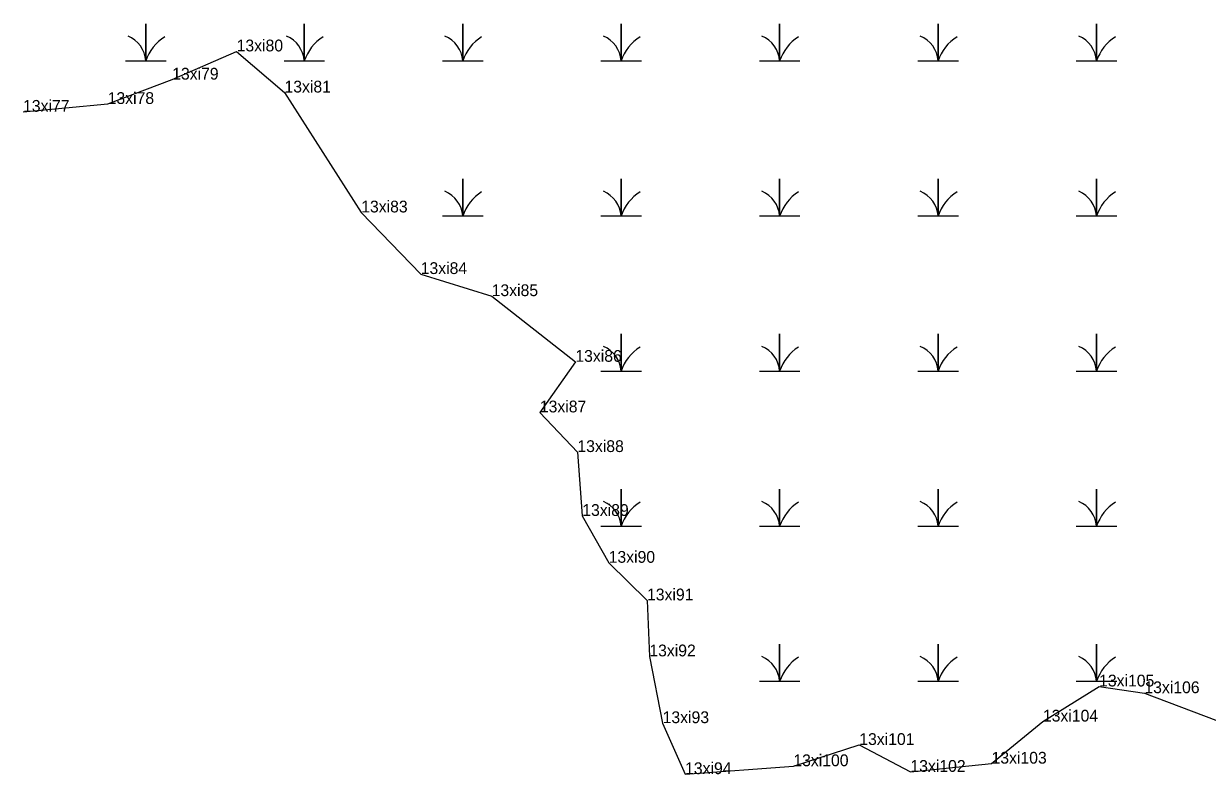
# Model space of a CAD drawing. Extents: x 2072529 to 2268796, y 436423 to 470406.
# Drawn here: x 2249251 to 2249753, y 445903 to 446222 of the extents above; entities that cross this region are included whole.
import ezdxf

# ---------------------------------------------------------------- set-up
doc = ezdxf.new("R2010")
doc.units = 0
for name, color, linetype in [('Exist Environmental Wetland Boundary Cogo Comment', 7, 'Continuous'), ('Exist Environmental Wetland Boundary Cogo Point CELL', 7, 'Continuous'), ('Old_Level_20', 7, 'Continuous')]:
    doc.layers.add(name, color=color, linetype=linetype)

msp = doc.modelspace()

# ---------------------------------------------------------------- linework, layer by layer
at = {"layer": 'Exist Environmental Wetland Boundary Cogo Point CELL'}
for points in [[(2249294.26, 446205.77), (2249302.86, 446205.77), (2249302.86, 446221.55), (2249302.86, 446205.77), (2249311.47, 446205.77)], [(2249361.51, 446205.77), (2249370.11, 446205.77), (2249370.11, 446221.55), (2249370.11, 446205.77), (2249378.72, 446205.77)], [(2249428.76, 446205.77), (2249437.36, 446205.77), (2249437.36, 446221.55), (2249437.36, 446205.77), (2249445.97, 446205.77)], [(2249496.01, 446205.77), (2249504.61, 446205.77), (2249504.61, 446221.55), (2249504.61, 446205.77), (2249513.22, 446205.77)], [(2249563.26, 446205.77), (2249571.86, 446205.77), (2249571.86, 446221.55), (2249571.86, 446205.77), (2249580.47, 446205.77)], [(2249630.51, 446205.77), (2249639.11, 446205.77), (2249639.11, 446221.55), (2249639.11, 446205.77), (2249647.72, 446205.77)], [(2249697.76, 446205.77), (2249706.36, 446205.77), (2249706.36, 446221.55), (2249706.36, 446205.77), (2249714.97, 446205.77)], [(2249428.76, 446139.97), (2249437.36, 446139.97), (2249437.36, 446155.75), (2249437.36, 446139.97), (2249445.97, 446139.97)], [(2249496.01, 446139.97), (2249504.61, 446139.97), (2249504.61, 446155.75), (2249504.61, 446139.97), (2249513.22, 446139.97)], [(2249563.26, 446139.97), (2249571.86, 446139.97), (2249571.86, 446155.75), (2249571.86, 446139.97), (2249580.47, 446139.97)], [(2249630.51, 446139.97), (2249639.11, 446139.97), (2249639.11, 446155.75), (2249639.11, 446139.97), (2249647.72, 446139.97)], [(2249697.76, 446139.97), (2249706.36, 446139.97), (2249706.36, 446155.75), (2249706.36, 446139.97), (2249714.97, 446139.97)], [(2249496.01, 446074.17), (2249504.61, 446074.17), (2249504.61, 446089.95), (2249504.61, 446074.17), (2249513.22, 446074.17)], [(2249563.26, 446074.17), (2249571.86, 446074.17), (2249571.86, 446089.95), (2249571.86, 446074.17), (2249580.47, 446074.17)], [(2249630.51, 446074.17), (2249639.11, 446074.17), (2249639.11, 446089.95), (2249639.11, 446074.17), (2249647.72, 446074.17)], [(2249697.76, 446074.17), (2249706.36, 446074.17), (2249706.36, 446089.95), (2249706.36, 446074.17), (2249714.97, 446074.17)], [(2249496.01, 446008.37), (2249504.61, 446008.37), (2249504.61, 446024.15), (2249504.61, 446008.37), (2249513.22, 446008.37)], [(2249563.26, 446008.37), (2249571.86, 446008.37), (2249571.86, 446024.15), (2249571.86, 446008.37), (2249580.47, 446008.37)], [(2249630.51, 446008.37), (2249639.11, 446008.37), (2249639.11, 446024.15), (2249639.11, 446008.37), (2249647.72, 446008.37)], [(2249697.76, 446008.37), (2249706.36, 446008.37), (2249706.36, 446024.15), (2249706.36, 446008.37), (2249714.97, 446008.37)], [(2249563.26, 445942.57), (2249571.86, 445942.57), (2249571.86, 445958.35), (2249571.86, 445942.57), (2249580.47, 445942.57)], [(2249630.51, 445942.57), (2249639.11, 445942.57), (2249639.11, 445958.35), (2249639.11, 445942.57), (2249647.72, 445942.57)], [(2249697.76, 445942.57), (2249706.36, 445942.57), (2249706.36, 445958.35), (2249706.36, 445942.57), (2249714.97, 445942.57)]]:
    msp.add_lwpolyline(points, dxfattribs=at)
for centre, radius, start, end in [((2249290.6, 446204.88), 12.3, 4.1403, 67.535), ((2249321.11, 446199.7), 19.22, 122.1274, 161.6222), ((2249357.85, 446204.88), 12.3, 4.1403, 67.535), ((2249388.36, 446199.7), 19.22, 122.1274, 161.6222), ((2249425.1, 446204.88), 12.3, 4.1403, 67.535), ((2249455.61, 446199.7), 19.22, 122.1274, 161.6222), ((2249492.35, 446204.88), 12.3, 4.1403, 67.535), ((2249522.86, 446199.7), 19.22, 122.1274, 161.6222), ((2249559.6, 446204.88), 12.3, 4.1403, 67.535), ((2249590.11, 446199.7), 19.22, 122.1274, 161.6222), ((2249626.85, 446204.88), 12.3, 4.1403, 67.535), ((2249657.36, 446199.7), 19.22, 122.1274, 161.6222), ((2249694.1, 446204.88), 12.3, 4.1403, 67.535), ((2249724.61, 446199.7), 19.22, 122.1274, 161.6222), ((2249425.1, 446139.08), 12.3, 4.1403, 67.535), ((2249455.61, 446133.9), 19.22, 122.1274, 161.6222), ((2249492.35, 446139.08), 12.3, 4.1403, 67.535), ((2249522.86, 446133.9), 19.22, 122.1274, 161.6222), ((2249559.6, 446139.08), 12.3, 4.1403, 67.535), ((2249590.11, 446133.9), 19.22, 122.1274, 161.6222), ((2249626.85, 446139.08), 12.3, 4.1403, 67.535), ((2249657.36, 446133.9), 19.22, 122.1274, 161.6222), ((2249694.1, 446139.08), 12.3, 4.1403, 67.535), ((2249724.61, 446133.9), 19.22, 122.1274, 161.6222), ((2249492.35, 446073.28), 12.3, 4.1403, 67.535), ((2249522.86, 446068.1), 19.22, 122.1274, 161.6222), ((2249559.6, 446073.28), 12.3, 4.1403, 67.535), ((2249590.11, 446068.1), 19.22, 122.1274, 161.6222), ((2249626.85, 446073.28), 12.3, 4.1403, 67.535), ((2249657.36, 446068.1), 19.22, 122.1274, 161.6222), ((2249694.1, 446073.28), 12.3, 4.1403, 67.535), ((2249724.61, 446068.1), 19.22, 122.1274, 161.6222), ((2249492.35, 446007.48), 12.3, 4.1403, 67.535), ((2249522.86, 446002.3), 19.22, 122.1274, 161.6222), ((2249559.6, 446007.48), 12.3, 4.1403, 67.535), ((2249590.11, 446002.3), 19.22, 122.1274, 161.6222), ((2249626.85, 446007.48), 12.3, 4.1403, 67.535), ((2249657.36, 446002.3), 19.22, 122.1274, 161.6222), ((2249694.1, 446007.48), 12.3, 4.1403, 67.535), ((2249724.61, 446002.3), 19.22, 122.1274, 161.6222), ((2249559.6, 445941.68), 12.3, 4.1403, 67.535), ((2249590.11, 445936.5), 19.22, 122.1274, 161.6222), ((2249626.85, 445941.68), 12.3, 4.1403, 67.535), ((2249657.36, 445936.5), 19.22, 122.1274, 161.6222), ((2249694.1, 445941.68), 12.3, 4.1403, 67.535), ((2249724.61, 445936.5), 19.22, 122.1274, 161.6222)]:
    msp.add_arc(centre, radius, start, end, dxfattribs=at)
at = {"layer": 'Old_Level_20'}
for p, q in [((2249341.41, 446209.79), (2249341.41, 446209.79)), ((2249314.05, 446197.82), (2249314.05, 446197.82)), ((2249361.72, 446192.35), (2249361.72, 446192.35)), ((2249286.67, 446187.49), (2249286.67, 446187.49)), ((2249394.28, 446141.46), (2249394.28, 446141.46)), ((2249419.53, 446115.35), (2249419.53, 446115.35)), ((2249449.65, 446105.97), (2249449.65, 446105.97)), ((2249485.16, 446078.11), (2249485.16, 446078.11)), ((2249470.1, 446056.65), (2249470.1, 446056.65)), ((2249486.03, 446039.83), (2249486.03, 446039.83)), ((2249488.1, 446012.73), (2249488.1, 446012.73)), ((2249499.3, 445992.85), (2249499.3, 445992.85)), ((2249515.58, 445976.9), (2249515.58, 445976.9)), ((2249516.56, 445953.16), (2249516.56, 445953.16)), ((2249707.45, 445940.39), (2249707.45, 445940.39)), ((2249726.67, 445937.54), (2249726.67, 445937.54)), ((2249683.6, 445925.5), (2249683.6, 445925.5)), ((2249522.21, 445924.83), (2249522.21, 445924.83)), ((2249605.66, 445915.57), (2249605.66, 445915.57)), ((2249577.68, 445906.57), (2249577.68, 445906.57)), ((2249661.79, 445907.65), (2249661.79, 445907.65)), ((2249531.73, 445903.2), (2249531.73, 445903.2)), ((2249627.37, 445904.17), (2249627.37, 445904.17))]:
    msp.add_line(p, q, dxfattribs=at)
for points in [[(2249250.77, 446184.17), (2249286.67, 446187.49), (2249314.05, 446197.82), (2249341.41, 446209.79), (2249361.72, 446192.35), (2249394.28, 446141.46), (2249419.53, 446115.35), (2249449.65, 446105.97), (2249485.16, 446078.11), (2249470.1, 446056.65), (2249486.03, 446039.83), (2249488.1, 446012.73), (2249499.3, 445992.85), (2249515.58, 445976.9), (2249516.56, 445953.16), (2249522.21, 445924.83), (2249531.73, 445903.2), (2249577.68, 445906.57)], [(2249577.68, 445906.57), (2249605.66, 445915.57), (2249627.37, 445904.17), (2249661.79, 445907.65), (2249683.6, 445925.5), (2249707.45, 445940.39), (2249726.67, 445937.54), (2249756.96, 445926.08)]]:
    msp.add_lwpolyline(points, dxfattribs=at)

# ---------------------------------------------------------------- texts
at = {"layer": 'Exist Environmental Wetland Boundary Cogo Comment'}
for s, p in [('13xi80', (2249341.41, 446209.79)), ('13xi79', (2249314.05, 446197.82)), ('13xi81', (2249361.72, 446192.35)), ('13xi78', (2249286.67, 446187.49)), ('13xi77', (2249250.77, 446184.17)), ('13xi83', (2249394.28, 446141.46)), ('13xi84', (2249419.53, 446115.35)), ('13xi85', (2249449.65, 446105.97)), ('13xi86', (2249485.16, 446078.11)), ('13xi87', (2249470.1, 446056.65)), ('13xi88', (2249486.03, 446039.83)), ('13xi89', (2249488.1, 446012.73)), ('13xi90', (2249499.3, 445992.85)), ('13xi91', (2249515.58, 445976.9)), ('13xi92', (2249516.56, 445953.16)), ('13xi105', (2249707.45, 445940.39)), ('13xi106', (2249726.67, 445937.54)), ('13xi93', (2249522.21, 445924.83)), ('13xi104', (2249683.6, 445925.5)), ('13xi101', (2249605.66, 445915.57)), ('13xi100', (2249577.68, 445906.57)), ('13xi103', (2249661.79, 445907.65)), ('13xi94', (2249531.73, 445903.2)), ('13xi102', (2249627.37, 445904.17))]:
    msp.add_text(s, height=5, dxfattribs=at).set_placement(p)

doc.saveas('drawing.dxf')
